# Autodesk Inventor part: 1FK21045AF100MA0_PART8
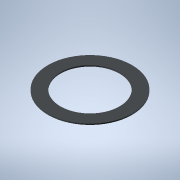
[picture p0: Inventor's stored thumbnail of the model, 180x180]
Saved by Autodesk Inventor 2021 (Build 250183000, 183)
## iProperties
Created: 2025-04
Part Number: 1FK21045AF100MA0_PART8
Material: Generic
Catalog Web Link: www.3dfindit.com
Description: -Servo synchronous motor
Document SubType Name: Modeling
Designer: psAdmin
Mass: 0.27214 g
Surface Area: 11.8752 cm^2
Volume: 0.27214 cm^3
Density: 1 g/cm^3
Appearance: PSOLRGB-212-217-219
Category: PARTsolutions
Title: 1FK21045AF100MA0_PART8
Author: Cadenas PARTsolutions
Comments: Servo synchronous motor
Sending System: PARTsolutions
Preprocessor: ST-DEVELOPER v19.3
PSOL_IDENT_0: {$CADENAS_DATA/23d-libs/siemens_ag/_cat_/52/6b/1fk21045af100ma0.prj},213 {VTYP=3D},{NB=1FK21045AF100
PSOL_IDENT_1: MA0_PART8},{LINA=1FK21045AF100MA0_PART8},{NN=1FK21045AF100MA0_PART8},{NOPRJ=TRUE},{DATE=19.08.2025 1
PSOL_IDENT_2: 4:00:38},{GEOMDATE=30.07.2025 02:01:45},{VERSION=},{LINEID=10},{WBVAR=},{WBNUMERIC=}  {NB=1FK21045AF
PSOL_IDENT_3: 100MA0_PART8},{LINA=1FK21045AF100MA0_PART8},{KT=DUMMY},{PREVIEW=../../../_pool_/cb/72/p_d211_xx_0043
PSOL_IDENT_4: 4j.png},{DESCSHORT=SIMOTICS S-1FK2 HD, SINAMICS S210 3AC 400V-480V, 2.4 Nm, 3000 rpm},{DESCLONG=SIMO
PSOL_IDENT_5: TICS S-1FK2 HD servo motor M0=2.4 Nm; PN = 0.75 kW at nN=3000 rpm (380-480 V); PN = 0.375 kW at nN=1
PSOL_IDENT_6: 500 rpm (200-240 V); with holding brake; degree of protection IP64; cylindrical shaft D19x40mm; abso
PSOL_IDENT_7: lute encoder 22-bit + 12-bit multiturn (encoder AM22DQC); with OCC interface; plug size M17, rotatab
PSOL_IDENT_8: le; SIMOTICS S-1FK2 servomotorfor a wide range of uses in industrial environments. SIMOTICS S‑1FK2 s
PSOL_IDENT_9: ervomotors are compact synchronous motors with a high dynamic performance that set themselves apart
PSOL_IDENT_10: as a result of their high power density, degree of protection and overload capability. The motors ar
PSOL_IDENT_11: e available in two variants: as High Dynamic variant (highest dynamic performance as a result of the
PSOL_IDENT_12: low intrinsic moment of inertia for applications demanding a high dynamic performance with low move
PSOL_IDENT_13: d masses) - and as Compact variant (precise and stable closed-loop control for medium up to large mo
PSOL_IDENT_14: ved masses as a result of a medium intrinsic moment of inertia). SIMOTICSS‑1FK2 servomotors fully ex
PSOL_IDENT_15: ploit their strengths in a system with the SINAMICSS210 frequency converter and simple connection us
PSOL_IDENT_16: ing the one cable connection (OCC). Advantages include the short control and positioning times, fast
PSOL_IDENT_17: and precise correction of disturbing quantities as well as stable control with a high dynamic perfo
PSOL_IDENT_18: rmance. The servo motors can be configured to address a wide range of requirements. For example with
PSOL_IDENT_19: and without holding brake, IP64 or IP65 degree of protection, singleturn or multiturn absolute enco
PSOL_IDENT_20: ders - to name just a few. Further, the servomotors are available in different shaft heights extendi
PSOL_IDENT_21: ng from 20 to 100. A shaft sealing ring is available to achieve an IP65 degree of protection and for
PSOL_IDENT_22: subsequent mounting at the motor or as spare part. SIMOTICS - the optimum motor for each and every
PSOL_IDENT_23: motion control application.},{INTNO=804766906411},{SUPPLIERALTNO=1FK2104-5AF10-0MA0},{MANUID=1FK2104
PSOL_IDENT_24: 5AF100MA0},{MANUNAME=Siemens},{MANUTYPEDESC=Synchronous motor 1FK2-HD 2.4 NM},{AAU732=SIMOTICS},{AAO
PSOL_IDENT_25: 057=S-1FK2},{AAU734=SIMOTICS S-1FK2 HD servo motor M0=2.4 Nm; PN = 0.75 kW at nN=3000 rpm (380-480 V
PSOL_IDENT_26: ); PN = 0.375 kW at nN=1500 rpm (200-240 V); with holding brake; degree of protection IP64; cylindri
PSOL_IDENT_27: cal shaft D19x40mm; absolute encoder 22-bit + 12-bit multiturn (encoder AM22DQC); with OCC interface
PSOL_IDENT_28: ; plug size M17, rotatable;},{AAW338=Synchronous motor 1FK2-HD 2.4 NM},{AAO742=SIMOTICS},{AAO663=404
PSOL_IDENT_29: 2948693070},{NOCUPEROU=1},{PRICEQUANTITY=1},{QUANTITYMIN=1},{QUANTITYINT=1},{CTN=85015100},{COO=DE},
PSOL_IDENT_30: {AAO676=1FK2104-5AF10-0MA0},{AAO677=Siemens AG},{ORDERUNIT=C62},{CONTENTUNIT=C62}
NB: 1FK21045AF100MA0_PART8
NT: Servo synchronous motor
NBSYN: $MANUID._PART8
LINA: 1FK21045AF100MA0_PART8
CATALOG: SIEMENS
PREVIEW: ../../../_pool_/cb/72/p_d211_xx_00434j.png
DESCSHORT: SIMOTICS S-1FK2 HD, SINAMICS S210 3AC 400V-480V, 2.4 Nm, 3000 rpm
DESCLONG: SIMOTICS S-1FK2 HD servo motor M0=2.4 Nm; PN = 0.75 kW at nN=3000 rpm (380-480 V); PN = 0.375 kW at nN=1500 rpm (200-240 V); with holding brake; degree of prote
INTNO: 804766906411
SUPPLIERALTNO: 1FK2104-5AF10-0MA0
MANUID: 1FK21045AF100MA0
MANUNAME: Siemens
MANUTYPEDESC: Synchronous motor 1FK2-HD 2.4 NM
AAU732: SIMOTICS
AAO057: S-1FK2
AAU734: SIMOTICS S-1FK2 HD servo motor M0=2.4 Nm; PN = 0.75 kW at nN=3000 rpm (380-480 V); PN = 0.375 kW at nN=1500 rpm (200-240 V); with holding brake; degree of prote
AAW338: Synchronous motor 1FK2-HD 2.4 NM
AAO742: SIMOTICS
AAO663: 4042948693070.0
NOCUPEROU: 1
PRICEQUANTITY: 1
QUANTITYMIN: 1
QUANTITYINT: 1
CTN: 85015100
COO: DE
ARTICLENO: 1FK21045AF100MA0_PART8
BOMINFO: 1FK21045AF100MA0_PART8
CREATOR: CADENAS GmbH
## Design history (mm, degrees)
feature "2025_04_17_15_34_52_0317"
body "Solid1"
